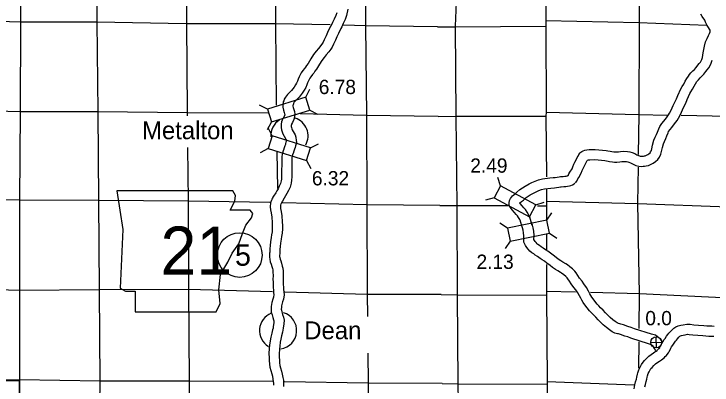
# Model space of a CAD drawing. Extents: x 77230 to 630905, y 790554 to 1662844.
# Drawn here: x 417367 to 458636, y 1525962 to 1547927 of the extents above; entities that cross this region are included whole.
import ezdxf

# ---------------------------------------------------------------- set-up
doc = ezdxf.new("R2010")
doc.units = 0
for name, color, linetype in [('Level 15', 7, 'Continuous'), ('Level 16', 7, 'Continuous'), ('Level 18', 7, 'Continuous'), ('Level 19', 7, 'Continuous'), ('Level 22', 7, 'Continuous'), ('Level 23', 7, 'Continuous'), ('Level 24', 7, 'Continuous'), ('Level 26', 7, 'Continuous'), ('Level 31', 7, 'Continuous'), ('Level 32', 7, 'Continuous'), ('Level 33', 7, 'Continuous'), ('Level 34', 7, 'Continuous'), ('Level 43', 7, 'Continuous')]:
    doc.layers.add(name, color=color, linetype=linetype)

msp = doc.modelspace()

# ---------------------------------------------------------------- linework, layer by layer
at = {"layer": 'Level 15'}
for points in [[(448831, 1550139), (448809, 1547534), (448818, 1547204), (448832, 1542116), (448818, 1541885), (448845, 1538277)], [(417724, 1549661), (417746, 1547411), (417738, 1542145), (417700, 1536906), (417692, 1531584), (417689, 1526263)], [(448850, 1537554), (448855, 1536846), (448859, 1536579), (448859, 1535749)], [(448859, 1534866), (448859, 1533963)], [(448859, 1533101), (448859, 1531515), (448852, 1531285), (448886, 1526167), (448883, 1526019), (448936, 1520658), (448930, 1517561)]]:
    msp.add_lwpolyline(points, dxfattribs=at)
at = {"layer": 'Level 16'}
for points in [[(443576, 1550063), (443443, 1547209), (443490, 1541869), (443556, 1536552), (443571, 1531308), (443601, 1526056), (443715, 1520734), (443786, 1515186), (443783, 1514888)], [(454344, 1550167), (454323, 1547392), (454305, 1541955), (454272, 1539602)], [(422260, 1549746), (422258, 1547455), (422316, 1542130), (422366, 1536889), (422412, 1531588), (422437, 1526179), (422367, 1520911)], [(427545, 1549814), (427576, 1547359), (427613, 1542132), (427616, 1541899)], [(432807, 1549902), (432827, 1547349), (432869, 1542521)], [(438157, 1550000), (438151, 1547225), (438203, 1541924), (438231, 1536631), (438242, 1531334), (438258, 1530010)], [(436061, 1547279), (432809, 1547351), (427556, 1547344), (422266, 1547433), (417736, 1547449), (412619, 1547591), (407365, 1547542)], [(442410, 1547155), (438155, 1547233), (436844, 1547262)], [(442410, 1547155), (443455, 1547163), (448818, 1547204)], [(448809, 1547534), (454311, 1547422), (458332, 1547272)], [(432389, 1542051), (427626, 1542078), (422314, 1542132), (417724, 1542133), (412562, 1542269), (407301, 1542250)], [(442442, 1541860), (438217, 1541920), (434295, 1542014)], [(442442, 1541860), (443498, 1541885), (448818, 1541885)], [(448832, 1542116), (454283, 1541977), (455995, 1541943)], [(456818, 1541927), (459561, 1541873), (464871, 1541688), (470074, 1541591), (475426, 1541500), (479337, 1541488)], [(432880, 1541638), (432882, 1541498)], [(427633, 1540013), (427661, 1536861), (427691, 1531632), (427728, 1526176), (427716, 1521298)], [(432909, 1539772), (432944, 1537605)], [(454262, 1538859), (454232, 1536726), (454325, 1531350), (454307, 1529319)], [(432490, 1536762), (427687, 1536847), (422362, 1536877), (417690, 1536898), (412508, 1536997), (407239, 1536976)], [(442542, 1536593), (438238, 1536623), (433232, 1536747)], [(442542, 1536593), (443564, 1536581), (446565, 1536580)], [(448310, 1536579), (448859, 1536579)], [(448855, 1536846), (454256, 1536704), (459594, 1536507), (464880, 1536429), (470166, 1536292), (475486, 1536116), (479463, 1535978)], [(432659, 1531489), (427691, 1531624), (422410, 1531596), (417703, 1531552), (412482, 1531716), (409819, 1531746)], [(448859, 1531515), (450567, 1531474)], [(442616, 1531327), (438256, 1531328), (433382, 1531469)], [(442616, 1531327), (443554, 1531310), (448852, 1531285)], [(451451, 1531453), (454351, 1531384), (459640, 1531119), (464841, 1530976), (470177, 1530877), (475503, 1530788), (478422, 1530692)], [(454299, 1528516), (454285, 1526971)], [(438285, 1527843), (438307, 1526089), (438354, 1520782)], [(432680, 1526167), (427710, 1526186), (422463, 1526193), (417689, 1526263)], [(442682, 1526056), (438301, 1526083), (433362, 1526160)], [(448886, 1526167), (454020, 1525973)], [(442682, 1526056), (443594, 1526038), (448883, 1526019)]]:
    msp.add_lwpolyline(points, dxfattribs=at)
at = {"layer": 'Level 18'}
msp.add_lwpolyline([(407401, 1549518), (407365, 1547542), (407301, 1542250), (407239, 1536976), (407211, 1531759), (409819, 1531746), (409752, 1526450), (412435, 1526374), (417689, 1526263), (417667, 1520973), (417653, 1515469), (417654, 1515315), (422612, 1515279), (427579, 1515225)], dxfattribs=at)
at = {"layer": 'Level 19'}
for p, q in [((434616, 1542997), (434861, 1543465)), ((432348, 1542289), (431880, 1542534)), ((434852, 1542241), (435319, 1541996)), ((432584, 1541533), (432338, 1541066)), ((432637, 1540713), (432393, 1541181)), ((434903, 1539999), (435372, 1540243)), ((432399, 1539957), (431931, 1539713)), ((434665, 1539243), (434909, 1538775)), ((446122, 1537749), (445969, 1538254)), ((445747, 1537051), (445241, 1536899)), ((448215, 1536624), (448720, 1536777)), ((448865, 1535725), (449158, 1536164)), ((447840, 1535927), (447992, 1535421)), ((446536, 1535256), (446096, 1535549)), ((449021, 1534948), (449461, 1534656)), ((446692, 1534480), (446400, 1534040))]:
    msp.add_line(p, q, dxfattribs=at)
for points in [[(432584, 1541533), (434852, 1542241), (434616, 1542997), (432348, 1542289)], [(432399, 1539957), (434665, 1539243), (434903, 1539999), (432637, 1540713)], [(445747, 1537051), (447840, 1535927), (448215, 1536624), (446122, 1537749)], [(448865, 1535725), (446536, 1535256), (446692, 1534480), (449021, 1534948)]]:
    msp.add_lwpolyline(points, close=True, dxfattribs=at)
at = {"layer": 'Level 22'}
for points in [[(436454, 1548002), (436388, 1547839), (436287, 1547609), (436203, 1547422), (436159, 1547330), (436009, 1547037), (435908, 1546819), (435819, 1546624), (435712, 1546389), (435656, 1546265), (435609, 1546198), (435500, 1546052), (435365, 1545887), (435229, 1545716), (435076, 1545520), (434917, 1545270), (434751, 1544996), (434662, 1544873), (434598, 1544772), (434547, 1544706), (434441, 1544570), (434352, 1544446), (434281, 1544327), (434228, 1544209), (434165, 1544064), (434121, 1543944), (434079, 1543830), (434020, 1543734), (433924, 1543592), (433769, 1543394), (433675, 1543301), (433537, 1543156), (433472, 1543081), (433411, 1543000), (433342, 1542883), (433319, 1542793), (433290, 1542720), (433256, 1542551), (433264, 1542402), (433294, 1542238), (433341, 1542086), (433367, 1542009), (433373, 1541972), (433371, 1541957), (433352, 1541896), (433287, 1541760), (433228, 1541634), (433191, 1541532), (433162, 1541399), (433164, 1541201), (433190, 1541064), (433222, 1540951), (433266, 1540832), (433334, 1540688), (433413, 1540555), (433445, 1540502), (433450, 1540491), (433459, 1540406), (433459, 1540385), (433447, 1540345), (433426, 1540259), (433410, 1540196), (433383, 1540124), (433326, 1539943), (433320, 1539928), (433281, 1539821), (433253, 1539756), (433237, 1539666), (433228, 1539611), (433206, 1539492), (433193, 1539275), (433199, 1539117), (433199, 1538946), (433191, 1538734), (433189, 1538301), (433183, 1538149), (433166, 1538041), (433121, 1537882), (433053, 1537731), (432977, 1537575), (432913, 1537461), (432841, 1537349), (432718, 1537148), (432676, 1537074), (432649, 1537023), (432621, 1536970), (432588, 1536889)], [(437111, 1548218), (437031, 1547828), (436941, 1547605), (436835, 1547365), (436747, 1547170), (436697, 1547065), (436548, 1546774), (436453, 1546570), (436366, 1546375), (436258, 1546140), (436181, 1545969), (436097, 1545848), (435973, 1545682), (435832, 1545509), (435700, 1545345), (435568, 1545174), (435427, 1544953), (435251, 1544663), (435158, 1544535), (435089, 1544427), (435022, 1544340), (434922, 1544210), (434854, 1544116), (434814, 1544050), (434777, 1543967), (434723, 1543842), (434685, 1543737), (434621, 1543566), (434524, 1543408), (434410, 1543239), (434218, 1542994), (434102, 1542881), (433983, 1542755), (433941, 1542706), (433911, 1542666), (433901, 1542649), (433890, 1542606), (433868, 1542551), (433860, 1542508), (433861, 1542472), (433878, 1542381), (433913, 1542269), (433949, 1542158), (433980, 1541991), (433960, 1541825), (433910, 1541673), (433829, 1541504), (433783, 1541405), (433769, 1541366), (433763, 1541338), (433764, 1541261), (433775, 1541201), (433793, 1541135), (433819, 1541066), (433864, 1540971), (433928, 1540864), (433984, 1540770), (434037, 1540637), (434059, 1540442), (434060, 1540333), (434044, 1540245), (434026, 1540186), (434008, 1540112), (433982, 1540014), (433950, 1539929), (433895, 1539753), (433885, 1539724), (433838, 1539597), (433831, 1539582), (433828, 1539564), (433818, 1539506), (433802, 1539421), (433794, 1539269), (433799, 1539127), (433799, 1538934), (433791, 1538721), (433789, 1538289), (433781, 1538092), (433753, 1537911), (433686, 1537676), (433597, 1537477), (433508, 1537296), (433427, 1537152), (433350, 1537031), (433236, 1536845), (433203, 1536786), (433179, 1536741), (433164, 1536713), (433143, 1536661)], [(450122, 1538354), (450139, 1538371), (450178, 1538454), (450238, 1538556), (450357, 1538761), (450407, 1538882), (450466, 1539030), (450533, 1539161), (450614, 1539322), (450664, 1539421), (450715, 1539514), (450761, 1539617), (450839, 1539703), (450887, 1539751), (450946, 1539788), (451012, 1539827), (451111, 1539861), (451239, 1539888), (451374, 1539898), (451720, 1539907), (452369, 1539843), (452479, 1539829), (452617, 1539809), (452707, 1539784), (452830, 1539764), (452892, 1539757), (452969, 1539760), (453107, 1539771), (453229, 1539790), (453392, 1539803), (453635, 1539788), (453767, 1539768), (453912, 1539731), (454073, 1539662), (454199, 1539594), (454338, 1539526), (454391, 1539513), (454460, 1539508), (454509, 1539513), (454575, 1539519), (454647, 1539527), (454687, 1539536), (454716, 1539548), (454847, 1539610), (454908, 1539653), (454969, 1539712), (455004, 1539762), (455049, 1539851), (455073, 1539934), (455118, 1540167), (455196, 1540456), (455283, 1540643), (455355, 1540792), (455411, 1540935), (455482, 1541128), (455552, 1541272), (455672, 1541438), (455784, 1541583), (455943, 1541781), (456069, 1541951), (456127, 1542052), (456226, 1542241), (456338, 1542504), (456440, 1542705), (456537, 1542900), (456616, 1543096), (456789, 1543487), (456872, 1543631), (456960, 1543770), (457054, 1543950), (457147, 1544105), (457241, 1544254), (457304, 1544344), (457387, 1544440), (457509, 1544561), (457593, 1544648), (457693, 1544757), (457805, 1544894), (457881, 1544988), (457950, 1545082), (457996, 1545155), (458029, 1545225), (458065, 1545348), (458101, 1545496), (458118, 1545634), (458157, 1545827), (458197, 1546017), (458255, 1546267), (458341, 1546473), (458424, 1546646), (458483, 1546774), (458523, 1546869), (458527, 1546888), (458516, 1546963), (458490, 1547026), (458427, 1547125), (458352, 1547249), (458258, 1547442), (458200, 1547552), (458058, 1547768), (457979, 1547913)], [(450557, 1537940), (450640, 1538028), (450709, 1538173), (450756, 1538252), (450895, 1538494), (450964, 1538657), (451013, 1538782), (451068, 1538888), (451150, 1539053), (451195, 1539142), (451252, 1539246), (451268, 1539280), (451271, 1539282), (451323, 1539292), (451405, 1539299), (451698, 1539306), (452301, 1539247), (452396, 1539235), (452495, 1539220), (452581, 1539197), (452744, 1539170), (452867, 1539155), (453006, 1539161), (453177, 1539175), (453299, 1539194), (453398, 1539202), (453572, 1539191), (453648, 1539180), (453717, 1539162), (453813, 1539121), (453925, 1539061), (454131, 1538959), (454299, 1538917), (454467, 1538907), (454563, 1538915), (454637, 1538922), (454746, 1538934), (454874, 1538962), (454965, 1539002), (455150, 1539090), (455289, 1539188), (455428, 1539319), (455520, 1539454), (455610, 1539630), (455657, 1539795), (455703, 1540032), (455762, 1540249), (455826, 1540387), (455905, 1540552), (455972, 1540721), (456035, 1540893), (456069, 1540963), (456152, 1541078), (456255, 1541211), (456419, 1541415), (456572, 1541622), (456653, 1541763), (456769, 1541984), (456883, 1542251), (456976, 1542435), (457085, 1542654), (457169, 1542863), (457325, 1543215), (457385, 1543320), (457480, 1543470), (457577, 1543656), (457659, 1543791), (457741, 1543922), (457777, 1543974), (457826, 1544030), (457935, 1544139), (458031, 1544237), (458146, 1544365), (458269, 1544514), (458356, 1544621), (458447, 1544744), (458524, 1544868), (458591, 1545011), (458645, 1545193)], [(455312, 1527995), (455231, 1528120), (455176, 1528225), (455155, 1528255), (455006, 1528370), (454883, 1528409), (453840, 1528735), (453662, 1528811), (453477, 1528865), (453224, 1528952), (453103, 1528989), (453043, 1529001), (452896, 1529043), (452730, 1529120), (452567, 1529224), (452390, 1529361), (452199, 1529528), (452062, 1529667), (451909, 1529829), (451769, 1529977), (451624, 1530114), (451503, 1530238), (451399, 1530351), (451244, 1530542), (451116, 1530701), (451018, 1530847), (450930, 1530992), (450877, 1531111), (450810, 1531242), (450708, 1531423), (450579, 1531605), (450474, 1531745), (450316, 1531947), (450207, 1532117), (450116, 1532245), (450072, 1532304), (449996, 1532382), (449867, 1532480), (449740, 1532581), (449674, 1532623), (449512, 1532720), (449373, 1532804), (449197, 1532928), (449058, 1533029), (448869, 1533173), (448722, 1533286), (448597, 1533381), (448467, 1533460), (448313, 1533568), (448188, 1533656), (448097, 1533725), (447989, 1533787), (447863, 1533893), (447771, 1534004), (447684, 1534106), (447615, 1534219), (447518, 1534412), (447505, 1534564), (447514, 1534792), (447498, 1534977), (447468, 1535127), (447434, 1535259), (447395, 1535386), (447329, 1535576), (447283, 1535718), (447268, 1535757), (447197, 1535870), (447125, 1535979), (447053, 1536062), (446959, 1536175), (446824, 1536327), (446763, 1536409), (446639, 1536590), (446638, 1536748), (446661, 1536876), (446730, 1537004), (446838, 1537157), (446996, 1537286), (447103, 1537370), (447280, 1537531), (447430, 1537634), (447581, 1537731), (447826, 1537871), (447979, 1537952), (448184, 1538034), (448370, 1538104), (448611, 1538174), (449047, 1538221), (449250, 1538240), (449356, 1538253), (449488, 1538273), (449591, 1538291), (449682, 1538299), (449825, 1538307), (449928, 1538319), (450010, 1538330), (450076, 1538341), (450093, 1538346), (450123, 1538358), (450128, 1538361), (450147, 1538377)], [(455705, 1528509), (455688, 1528541), (455592, 1528675), (455289, 1528910), (455063, 1528982), (454048, 1529299), (453864, 1529377), (453659, 1529437), (453409, 1529523), (453246, 1529573), (453181, 1529585), (453107, 1529606), (453019, 1529647), (452912, 1529715), (452771, 1529824), (452611, 1529964), (452494, 1530084), (452345, 1530242), (452194, 1530401), (452045, 1530542), (451939, 1530650), (451854, 1530744), (451710, 1530920), (451600, 1531057), (451524, 1531170), (451462, 1531272), (451418, 1531370), (451339, 1531526), (451215, 1531745), (451064, 1531958), (450951, 1532109), (450806, 1532295), (450705, 1532452), (450601, 1532599), (450529, 1532696), (450394, 1532833), (450234, 1532954), (450091, 1533068), (449991, 1533133), (449820, 1533235), (449701, 1533306), (449547, 1533416), (449416, 1533511), (449234, 1533649), (449087, 1533763), (448934, 1533879), (448794, 1533963), (448658, 1534058), (448542, 1534141), (448428, 1534227), (448334, 1534280), (448290, 1534318), (448230, 1534390), (448171, 1534460), (448139, 1534511), (448106, 1534577), (448106, 1534577), (448115, 1534806), (448093, 1535062), (448053, 1535260), (448012, 1535420), (447966, 1535573), (447898, 1535767), (447850, 1535917), (447808, 1536026), (447701, 1536196), (447603, 1536343), (447510, 1536451), (447414, 1536566), (447290, 1536705), (447271, 1536731), (447280, 1536744), (447370, 1536817), (447490, 1536911), (447653, 1537060), (447763, 1537134), (447893, 1537219), (448115, 1537345), (448231, 1537406), (448401, 1537474), (448560, 1537534), (448728, 1537583), (449107, 1537624), (449316, 1537643), (449439, 1537659), (449584, 1537681), (449669, 1537695), (449726, 1537700), (449876, 1537709), (450002, 1537723), (450100, 1537737), (450211, 1537755), (450290, 1537778), (450393, 1537819), (450480, 1537873), (450533, 1537917)], [(432580, 1536867), (432538, 1536739), (432518, 1536519), (432537, 1536328), (432566, 1536146), (432606, 1535907), (432628, 1535593), (432634, 1535393), (432637, 1535222), (432625, 1535022), (432599, 1534845), (432572, 1534686), (432536, 1534432), (432508, 1534220), (432493, 1534028), (432485, 1533819), (432482, 1533776), (432474, 1533673), (432472, 1533538), (432487, 1533407), (432521, 1533260), (432567, 1533116), (432612, 1532988), (432648, 1532859), (432665, 1532774), (432680, 1532667), (432681, 1532432), (432678, 1532239), (432684, 1532050), (432687, 1531901), (432693, 1531731), (432701, 1531579), (432717, 1531411), (432727, 1531318), (432706, 1531168), (432672, 1531052), (432616, 1530857), (432596, 1530735), (432579, 1530618), (432568, 1530453), (432581, 1530282), (432628, 1530121), (432677, 1529966), (432716, 1529831), (432731, 1529756), (432727, 1529645), (432696, 1529422), (432681, 1529336), (432655, 1529227), (432607, 1529025), (432551, 1528803), (432510, 1528587), (432478, 1528325), (432459, 1528131), (432443, 1527823), (432453, 1527566), (432461, 1527409), (432478, 1527207), (432502, 1527021), (432547, 1526828), (432610, 1526617), (432646, 1526479), (432678, 1526315), (432697, 1526178), (432708, 1526074), (432702, 1525954)], [(433151, 1536683), (433130, 1536618), (433121, 1536521), (433133, 1536405), (433159, 1536243), (433203, 1535977), (433227, 1535623), (433234, 1535407), (433238, 1535209), (433222, 1534960), (433192, 1534752), (433165, 1534594), (433130, 1534351), (433105, 1534158), (433092, 1533993), (433084, 1533785), (433080, 1533732), (433074, 1533647), (433073, 1533569), (433080, 1533508), (433100, 1533419), (433136, 1533308), (433185, 1533168), (433232, 1532998), (433257, 1532875), (433280, 1532710), (433281, 1532428), (433278, 1532245), (433284, 1532066), (433287, 1531918), (433293, 1531756), (433299, 1531623), (433314, 1531471), (433331, 1531308), (433295, 1531041), (433248, 1530884), (433203, 1530725), (433189, 1530642), (433176, 1530555), (433169, 1530456), (433175, 1530390), (433202, 1530295), (433251, 1530140), (433299, 1529975), (433334, 1529805), (433325, 1529592), (433289, 1529330), (433269, 1529215), (433238, 1529087), (433190, 1528884), (433137, 1528673), (433103, 1528495), (433075, 1528260), (433057, 1528085), (433043, 1527820), (433053, 1527593), (433060, 1527449), (433074, 1527271), (433093, 1527128), (433127, 1526982), (433188, 1526778), (433231, 1526612), (433270, 1526416), (433293, 1526249), (433309, 1526089), (433298, 1525872)]]:
    msp.add_lwpolyline(points, dxfattribs=at)
at = {"layer": 'Level 23'}
for points in [[(455484, 1528097), (455534, 1528162), (455549, 1528203), (455647, 1528382), (455671, 1528428), (455724, 1528523), (455807, 1528660), (455855, 1528726), (455941, 1528856), (456023, 1528962), (456084, 1529026), (456141, 1529094), (456249, 1529211), (456382, 1529337), (456505, 1529403), (456633, 1529465), (456794, 1529504), (456919, 1529532), (457148, 1529573), (457343, 1529561), (457563, 1529532), (457836, 1529516), (458147, 1529491), (458328, 1529473), (458472, 1529460), (458620, 1529460), (458757, 1529451)], [(455929, 1527692), (456065, 1527867), (456097, 1527954), (456174, 1528096), (456197, 1528139), (456243, 1528221), (456308, 1528329), (456348, 1528384), (456429, 1528506), (456478, 1528569), (456533, 1528627), (456592, 1528699), (456675, 1528788), (456738, 1528847), (456779, 1528869), (456836, 1528897), (456931, 1528920), (457038, 1528944), (457182, 1528970), (457285, 1528963), (457506, 1528934), (457795, 1528917), (458094, 1528893), (458271, 1528876), (458444, 1528859), (458601, 1528860), (458733, 1528851)], [(454118, 1526160), (454161, 1526306), (454183, 1526438), (454222, 1526605), (454251, 1526690), (454298, 1526862), (454379, 1527024), (454466, 1527182), (454556, 1527310), (454649, 1527413), (454767, 1527541), (454896, 1527671), (455038, 1527777), (455184, 1527872), (455256, 1527926), (455324, 1527962), (455384, 1528004), (455415, 1528045), (455487, 1528118), (455554, 1528163)], [(454694, 1525992), (454747, 1526172), (454771, 1526320), (454799, 1526438), (454825, 1526514), (454861, 1526647), (454911, 1526746), (454976, 1526864), (455025, 1526934), (455092, 1527008), (455201, 1527126), (455291, 1527217), (455381, 1527285), (455527, 1527379), (455579, 1527418), (455639, 1527451), (455804, 1527566), (455868, 1527650), (455871, 1527653), (455929, 1527692)], [(454025, 1525743), (454074, 1525982), (454115, 1526148)], [(454660, 1525850), (454698, 1526005)]]:
    msp.add_lwpolyline(points, dxfattribs=at)
at = {"layer": 'Level 24'}
msp.add_lwpolyline([(423458, 1537451), (423800, 1535167), (423648, 1531704), (423952, 1531513), (424523, 1531513), (424523, 1530295), (429320, 1530295), (429548, 1530790), (429472, 1531589), (429586, 1532503), (430005, 1533226), (430271, 1533759), (430652, 1534330), (430880, 1534939), (431071, 1535434), (431413, 1535853), (431489, 1536119), (431337, 1536309), (430157, 1536309), (430424, 1536842), (430462, 1537185), (430304, 1537448)], close=True, dxfattribs=at)
at = {"layer": 'Level 26'}
for centre, start, end in [((433653, 1540715), 122.55, 183.0665), ((433653, 1540715), 330.6423, 72.2161), ((432981, 1529188), 111.413, 238.6713), ((432981, 1529188), 278.5836, 73.2016)]:
    msp.add_arc(centre, 1100, start, end, dxfattribs=at)
at = {"layer": 'Level 33'}
msp.add_circle((430717, 1533656), 1320, dxfattribs=at)
at = {"layer": 'Level 34'}
for p, q in [((455343, 1528164), (455328, 1528815)), ((455010, 1528482), (455661, 1528497))]:
    msp.add_line(p, q, dxfattribs=at)
msp.add_circle((455336, 1528489), 326, dxfattribs=at)
at = {"layer": 'Level 43'}
msp.add_lwpolyline([(409779, 1527532), (409762, 1526430), (412433, 1526346), (412918, 1526325), (415195, 1526271), (416735, 1526233), (417678, 1526221), (417678, 1526157), (417668, 1524635)], dxfattribs=at)

# ---------------------------------------------------------------- texts
at = {"layer": 'Level 24'}
msp.add_text('21', height=2851.2, dxfattribs=at).set_placement((426031, 1532492))
at = {"layer": 'Level 26'}
for s, p in [('Metalton', (424938, 1540511)), ('Dean', (434530, 1528673))]:
    msp.add_text(s, height=1056, dxfattribs=at).set_placement(p)
at = {"layer": 'Level 31'}
msp.add_text('0.0', height=844.8, dxfattribs=at).set_placement((454692, 1529501))
at = {"layer": 'Level 32'}
for s, p in [('6.78', (435386, 1543185)), ('2.49', (444344, 1538530)), ('6.32', (434980, 1537781)), ('2.13', (444712, 1532838))]:
    msp.add_text(s, height=844.8, dxfattribs=at).set_placement(p)
at = {"layer": 'Level 33'}
msp.add_text('5', height=1267, dxfattribs=at).set_placement((430434, 1533023))

doc.saveas('drawing.dxf')
